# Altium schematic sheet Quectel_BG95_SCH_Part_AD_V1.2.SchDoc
size A1
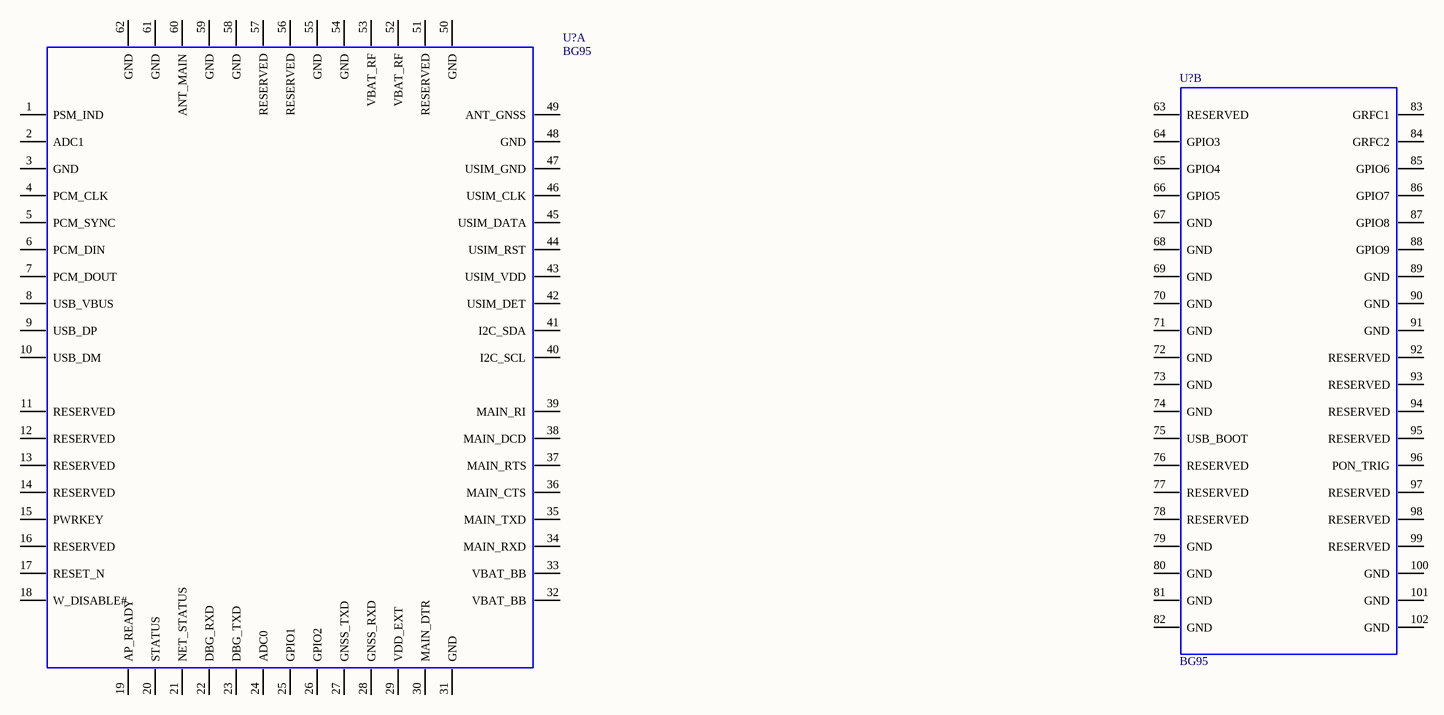
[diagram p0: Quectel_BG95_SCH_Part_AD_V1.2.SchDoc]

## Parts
(Parts that share a designator on the sheet are numbered #1, #2 ... from top to bottom, then left to right.)
U?#1  BG95  (part A of 2)
U?#2  BG95  (part B of 2)

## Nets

Not connected (* = marked no-connect by the designer): U?#1 1(PSM_IND) 2(ADC1) 3(GND) 4(PCM_CLK) 5(PCM_SYNC) 6(PCM_DIN) 7(PCM_DOUT) 8(USB_VBUS) 9(USB_DP) 10(USB_DM) 11(RESERVED) 12(RESERVED) 13(RESERVED) 14(RESERVED) 15(PWRKEY) 16(RESERVED) 17(RESET_N) 18(W_DISABLE#) 19(AP_READY) 20(STATUS) 21(NET_STATUS) 22(DBG_RXD) 23(DBG_TXD) 24(ADC0) 25(GPIO1) 26(GPIO2) 27(GNSS_TXD) 28(GNSS_RXD) 29(VDD_EXT) 30(MAIN_DTR) 31(GND) 32(VBAT_BB) 33(VBAT_BB) 34(MAIN_RXD) 35(MAIN_TXD) 36(MAIN_CTS) 37(MAIN_RTS) 38(MAIN_DCD) 39(MAIN_RI) 40(I2C_SCL) 41(I2C_SDA) 42(USIM_DET) 43(USIM_VDD) 44(USIM_RST) 45(USIM_DATA) 46(USIM_CLK) 47(USIM_GND) 48(GND) 49(ANT_GNSS) 50(GND) 51(RESERVED) 52(VBAT_RF) 53(VBAT_RF) 54(GND) 55(GND) 56(RESERVED) 57(RESERVED) 58(GND) 59(GND) 60(ANT_MAIN) 61(GND) 62(GND); U?#2 63(RESERVED) 64(GPIO3) 65(GPIO4) 66(GPIO5) 67(GND) 68(GND) 69(GND) 70(GND) 71(GND) 72(GND) 73(GND) 74(GND) 75(USB_BOOT) 76(RESERVED) 77(RESERVED) 78(RESERVED) 79(GND) 80(GND) 81(GND) 82(GND) 83(GRFC1) 84(GRFC2) 85(GPIO6) 86(GPIO7) 87(GPIO8) 88(GPIO9) 89(GND) 90(GND) 91(GND) 92(RESERVED) 93(RESERVED) 94(RESERVED) 95(RESERVED) 96(PON_TRIG) 97(RESERVED) 98(RESERVED) 99(RESERVED) 100(GND) 101(GND) 102(GND)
